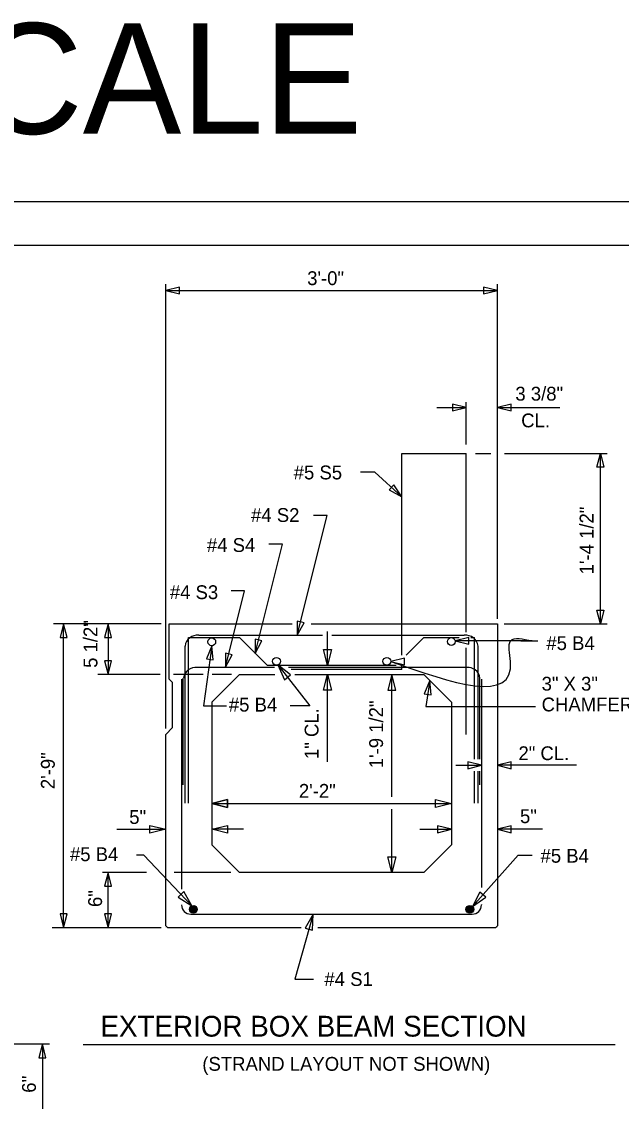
# Model space of a CAD drawing. Extents: x -38 to 94, y -165 to 80.
# Drawn here: x -18.57 to -13.15, y -151.14 to -141.37 of the extents above; entities that cross this region are included whole.
import ezdxf

# ---------------------------------------------------------------- set-up
doc = ezdxf.new("R2010")
doc.units = 0
for name, color, linetype in [('Arrowhead Terminators', 7, 'Continuous'), ('Arrowhead Terminators CELL', 7, 'Continuous'), ('Box Beam', 7, 'Continuous'), ('Dimension Lines', 7, 'Continuous'), ('Plan Sheet CELL', 7, 'Continuous'), ('Plot Shape CELL', 7, 'Continuous'), ('Rebar Lines', 7, 'Continuous'), ('Subtitle Text', 7, 'Continuous'), ('Text', 7, 'Continuous'), ('User Information Notes', 7, 'Continuous')]:
    doc.layers.add(name, color=color, linetype=linetype)

msp = doc.modelspace()

# ---------------------------------------------------------------- linework, layer by layer
at = {"layer": 'Arrowhead Terminators'}
for points in [[(-13.3685, -145.4052), (-13.3373, -145.2802), (-13.306, -145.4052)], [(-13.306, -146.6968), (-13.3373, -146.8218), (-13.3685, -146.6968)], [(-15.7707, -147.0532), (-15.8065, -147.1963), (-15.8423, -147.0532)], [(-15.2334, -147.1624), (-15.1084, -147.1936), (-15.1084, -147.1311)], [(-16.255, -147.194), (-16.1952, -147.3282), (-16.1391, -147.2843)], [(-15.8423, -147.4232), (-15.8065, -147.2802), (-15.7707, -147.4232)], [(-15.2232, -147.2802), (-15.2588, -147.4227), (-15.1875, -147.4227)], [(-16.7095, -148.4838), (-16.8525, -148.4481), (-16.7095, -148.4124)], [(-16.7095, -148.4124), (-16.8525, -148.4481), (-16.7095, -148.4838)], [(-14.8286, -148.4124), (-14.6856, -148.4481), (-14.8286, -148.4838)], [(-17.4122, -148.6452), (-17.2692, -148.681), (-17.4122, -148.7168)], [(-16.7095, -148.7168), (-16.8525, -148.681), (-16.7095, -148.6452)], [(-15.1874, -148.9288), (-15.2232, -149.0718), (-15.2589, -148.9288)], [(-17.0336, -149.3729), (-17.1058, -149.245), (-17.1575, -149.294)], [(-14.4956, -149.3786), (-14.374, -149.2962), (-14.4271, -149.2487)], [(-15.936, -149.4482), (-16.009, -149.5757), (-15.9404, -149.5951)], [(-18.3841, -150.6233), (-18.4153, -150.7483), (-18.3528, -150.7483)]]:
    msp.add_lwpolyline(points, close=True, dxfattribs=at)
at = {"layer": 'Arrowhead Terminators CELL'}
for points in [[(-17.2692, -143.8054), (-17.1442, -143.8367), (-17.1442, -143.7742)], [(-14.2689, -143.8054), (-14.3939, -143.7742), (-14.3939, -143.8367)], [(-14.5502, -144.8644), (-14.6752, -144.8331), (-14.6752, -144.8956)], [(-14.2689, -144.8644), (-14.1439, -144.8956), (-14.1439, -144.8331)], [(-15.1335, -145.6713), (-15.2052, -145.5642), (-15.2471, -145.6105)], [(-18.1922, -146.8218), (-18.2234, -146.9468), (-18.1609, -146.9468)], [(-17.7902, -146.8218), (-17.8214, -146.9468), (-17.7589, -146.9468)], [(-16.0786, -146.9258), (-16.0182, -146.812), (-16.0788, -146.797)], [(-14.651, -146.9753), (-14.526, -147.0066), (-14.526, -146.9441)], [(-16.8525, -147.02), (-16.9006, -147.1395), (-16.8387, -147.1481)], [(-16.4592, -147.0895), (-16.3988, -146.9757), (-16.4594, -146.9607)], [(-16.7275, -147.2151), (-16.6671, -147.1013), (-16.7277, -147.0863)], [(-17.7902, -147.2802), (-17.7589, -147.1552), (-17.8214, -147.1552)], [(-14.8808, -147.3351), (-14.9307, -147.4539), (-14.8689, -147.4634)], [(-14.4119, -148.1013), (-14.5369, -148.07), (-14.5369, -148.1325)], [(-14.2689, -148.1013), (-14.1439, -148.1325), (-14.1439, -148.07)], [(-14.6856, -148.681), (-14.8106, -148.6498), (-14.8106, -148.7123)], [(-14.2689, -148.681), (-14.1439, -148.7123), (-14.1439, -148.6498)], [(-17.7902, -149.0718), (-17.8214, -149.1968), (-17.7589, -149.1968)], [(-18.1922, -149.5718), (-18.1609, -149.4468), (-18.2234, -149.4468)], [(-17.7902, -149.5718), (-17.7589, -149.4468), (-17.8214, -149.4468)]]:
    msp.add_lwpolyline(points, close=True, dxfattribs=at)
at = {"layer": 'Box Beam'}
for p, q in [((-17.238, -147.3219), (-17.238, -146.8218)), ((-17.238, -146.8218), (-16.126, -146.8218)), ((-15.9532, -146.8218), (-14.2689, -146.8218)), ((-14.2689, -146.8218), (-14.2689, -149.554)), ((-17.2067, -147.3531), (-17.238, -147.3219)), ((-16.8525, -147.5303), (-16.6024, -147.2802)), ((-16.6024, -147.2802), (-16.2814, -147.2802)), ((-16.102, -147.2802), (-14.9356, -147.2802)), ((-14.9356, -147.2802), (-14.6856, -147.5303)), ((-17.2067, -147.7594), (-17.2067, -147.3531)), ((-16.8525, -147.5303), (-16.8525, -148.8218)), ((-14.6856, -147.5303), (-14.6856, -148.8218)), ((-17.2692, -147.8219), (-17.2067, -147.7594)), ((-17.2692, -149.554), (-17.2692, -147.8219)), ((-16.6024, -149.0718), (-16.8525, -148.8218)), ((-14.6856, -148.8218), (-14.9356, -149.0718)), ((-14.9356, -149.0718), (-16.6024, -149.0718)), ((-17.2692, -149.554), (-17.2513, -149.5718)), ((-16.0429, -149.5718), (-17.2513, -149.5718)), ((-14.2867, -149.5718), (-15.8938, -149.5718)), ((-14.2688, -149.554), (-14.2867, -149.5718))]:
    msp.add_line(p, q, dxfattribs=at)
at = {"layer": 'Dimension Lines'}
for p, q in [((-17.2692, -147.7691), (-17.2692, -143.7487)), ((-17.2692, -143.8054), (-14.2689, -143.8054)), ((-14.2689, -146.7758), (-14.2689, -143.7487)), ((-14.8155, -144.8644), (-14.5502, -144.8644)), ((-14.5502, -145.1981), (-14.5502, -144.8159)), ((-14.2689, -144.8644), (-13.7045, -144.8644)), ((-14.4681, -145.2802), (-14.3278, -145.2802)), ((-14.2051, -145.2802), (-13.2752, -145.2802)), ((-13.3373, -146.8218), (-13.3373, -145.2802)), ((-17.3095, -146.8218), (-18.2832, -146.8218)), ((-18.1922, -149.5718), (-18.1922, -146.8218)), ((-17.7902, -146.8218), (-17.7902, -147.2802)), ((-14.2064, -146.8218), (-13.2752, -146.8218)), ((-15.8065, -147.1963), (-15.8065, -146.8908)), ((-13.955, -146.9753), (-14.651, -146.9753)), ((-17.3186, -147.2802), (-17.8841, -147.2802)), ((-16.9303, -147.2802), (-17.1974, -147.2802)), ((-16.674, -147.2802), (-16.8504, -147.2802)), ((-15.8065, -148.0719), (-15.8065, -147.2802)), ((-15.2232, -148.3888), (-15.2232, -147.2802)), ((-14.644, -148.1013), (-14.4119, -148.1013)), ((-13.554, -148.1013), (-14.2689, -148.1013)), ((-16.8525, -148.4481), (-14.6856, -148.4481)), ((-15.2232, -149.0718), (-15.2232, -148.4985)), ((-17.7109, -148.681), (-17.2692, -148.681)), ((-16.5664, -148.681), (-16.8525, -148.681)), ((-14.9717, -148.681), (-14.6856, -148.681)), ((-13.8599, -148.681), (-14.2689, -148.681)), ((-14.0822, -148.9164), (-13.9553, -148.9164)), ((-17.4438, -149.0718), (-17.8398, -149.0718)), ((-17.7902, -149.5718), (-17.7902, -149.0718)), ((-16.6793, -149.0718), (-17.1938, -149.0718)), ((-15.936, -149.4482), (-16.1025, -150.0382)), ((-17.3095, -149.5718), (-18.2949, -149.5718)), ((-16.1025, -150.0382), (-15.9338, -150.0382)), ((-19.0939, -150.6233), (-18.3216, -150.6233)), ((-18.3841, -150.6233), (-18.3841, -151.3733))]:
    msp.add_line(p, q, dxfattribs=at)
for points in [[(-15.1335, -145.6713), (-15.3789, -145.4491), (-15.5063, -145.4491)], [(-16.0786, -146.9258), (-15.8097, -145.8428), (-15.9321, -145.8428)], [(-16.4592, -147.0895), (-16.214, -146.1018), (-16.3364, -146.1018)], [(-16.7275, -147.2151), (-16.5557, -146.5231), (-16.6781, -146.5231)], [(-16.8525, -147.02), (-16.9277, -147.564), (-16.7201, -147.564)], [(-14.0561, -146.9753), (-13.902, -146.9753)], [(-16.255, -147.194), (-15.9653, -147.564), (-16.1448, -147.564)], [(-14.8808, -147.3351), (-14.9169, -147.5696), (-13.9252, -147.5696)], [(-17.0336, -149.3729), (-17.4661, -148.9164), (-17.5348, -148.9164)], [(-14.4956, -149.3786), (-14.0822, -148.9164)]]:
    msp.add_lwpolyline(points, dxfattribs=at)
msp.add_spline([(-15.2334, -147.1624), (-14.1496, -147.1624), (-14.1496, -146.9753), (-13.955, -146.9753)], degree=3, dxfattribs=at)
at = {"layer": 'Plan Sheet CELL'}
msp.add_line((-32.4443, -143.3938), (-0.4439, -143.3938), dxfattribs=at)
at = {"layer": 'Plot Shape CELL'}
msp.add_lwpolyline([(-33.4983, -142.9999), (-0.4352, -142.9999), (-0.4352, -164.9999), (-33.4983, -164.9999)], close=True, dxfattribs=at)
at = {"layer": 'Rebar Lines'}
for p, q in [((-15.1335, -145.2802), (-14.5502, -145.2802)), ((-15.1335, -147.1064), (-15.1335, -145.2802)), ((-14.5502, -146.8982), (-14.5502, -145.2802)), ((-17.0628, -146.9463), (-16.6025, -146.9463)), ((-17.0628, -148.4443), (-17.0628, -146.9463)), ((-16.9698, -146.9258), (-15.85, -146.9258)), ((-16.6025, -146.9463), (-16.3524, -147.1963)), ((-15.7677, -146.9258), (-14.5691, -146.9258)), ((-14.9356, -146.9463), (-15.0948, -147.1054)), ((-14.9356, -146.9463), (-14.616, -146.9463)), ((-14.5104, -146.9463), (-14.4754, -146.9463)), ((-14.4754, -148.0472), (-14.4754, -146.9463)), ((-17.0941, -148.4443), (-17.0941, -147.0226)), ((-14.5502, -147.8218), (-14.5502, -147.0391)), ((-14.4441, -148.0472), (-14.4441, -147.0226)), ((-16.9821, -147.2151), (-16.2839, -147.2151)), ((-16.3524, -147.1963), (-15.1857, -147.1963)), ((-16.1599, -147.2151), (-14.5252, -147.2151)), ((-15.1335, -147.2346), (-16.1335, -147.2346)), ((-15.1335, -147.2346), (-15.1335, -147.2037)), ((-17.1254, -147.3219), (-17.1254, -149.2229)), ((-17.1106, -148.2802), (-17.1106, -147.3131)), ((-14.4279, -148.0472), (-14.4279, -147.3098)), ((-14.4128, -147.3219), (-14.4128, -149.2091)), ((-14.4754, -148.4443), (-14.4754, -148.1561)), ((-14.4441, -148.4443), (-14.4441, -148.1561)), ((-14.4279, -148.2802), (-14.4279, -148.1561)), ((-14.4128, -149.3604), (-14.4128, -149.3648)), ((-17.042, -149.4482), (-14.4962, -149.4482))]:
    msp.add_line(p, q, dxfattribs=at)
for points in [[(-17.0211, -149.3718), (-17.0084, -149.3743), (-16.9977, -149.3815), (-16.9906, -149.3922), (-16.988, -149.4049), (-16.9906, -149.4175), (-16.9977, -149.4282), (-17.0084, -149.4354), (-17.0211, -149.4379), (-17.0338, -149.4354), (-17.0446, -149.4282), (-17.0517, -149.4175), (-17.0542, -149.4049), (-17.0517, -149.3922), (-17.0446, -149.3815), (-17.0338, -149.3743), (-17.0211, -149.3718), (-17.0211, -149.4049), (-17.0211, -149.4379), (-17.0084, -149.4354), (-17.0211, -149.4049), (-16.9977, -149.4282), (-16.9906, -149.4175), (-17.0211, -149.4049), (-16.988, -149.4049), (-16.9906, -149.3922), (-17.0211, -149.4049), (-16.9977, -149.3815), (-17.0084, -149.3743), (-17.0211, -149.4049), (-17.0338, -149.3743), (-17.0446, -149.3815), (-17.0211, -149.4049), (-17.0517, -149.3922), (-17.0542, -149.4049), (-17.0211, -149.4049), (-17.0517, -149.4175), (-17.0446, -149.4282), (-17.0211, -149.4049), (-17.0338, -149.4354)], [(-14.517, -149.3718), (-14.5043, -149.3743), (-14.4936, -149.3815), (-14.4865, -149.3922), (-14.4839, -149.4049), (-14.4865, -149.4175), (-14.4936, -149.4282), (-14.5043, -149.4354), (-14.517, -149.4379), (-14.5297, -149.4354), (-14.5405, -149.4282), (-14.5475, -149.4175), (-14.5501, -149.4049), (-14.5475, -149.3922), (-14.5405, -149.3815), (-14.5297, -149.3743), (-14.517, -149.3718), (-14.517, -149.4049), (-14.517, -149.4379), (-14.5043, -149.4354), (-14.517, -149.4049), (-14.4936, -149.4282), (-14.4865, -149.4175), (-14.517, -149.4049), (-14.4839, -149.4049), (-14.4865, -149.3922), (-14.517, -149.4049), (-14.4936, -149.3815), (-14.5043, -149.3743), (-14.517, -149.4049), (-14.5297, -149.3743), (-14.5405, -149.3815), (-14.517, -149.4049), (-14.5475, -149.3922), (-14.5501, -149.4049), (-14.517, -149.4049), (-14.5475, -149.4175), (-14.5405, -149.4282), (-14.517, -149.4049), (-14.5297, -149.4354)]]:
    msp.add_lwpolyline(points, dxfattribs=at)
for centre in [(-16.8525, -146.9847), (-14.6856, -146.9821), (-16.2674, -147.1611), (-15.2686, -147.1611), (-17.0194, -149.4052), (-14.5187, -149.4052)]:
    msp.add_circle(centre, 0.0352, dxfattribs=at)
for centre, radius, start, end in [((-16.9835, -147.0363), 0.1114, 82.91815, 172.91815), ((-14.5549, -147.0367), 0.1118, 7.25072, 97.25072), ((-16.9968, -147.3272), 0.1114, 82.91815, 172.91815), ((-14.5373, -147.3275), 0.1118, 7.25072, 97.25072), ((-17.042, -149.3648), 0.0834, 180, 270), ((-14.4962, -149.3648), 0.0834, 270, 360)]:
    msp.add_arc(centre, radius, start, end, dxfattribs=at)
at = {"layer": 'Subtitle Text'}
msp.add_line((-18.015, -150.6289), (-13.2046, -150.6289), dxfattribs=at)
at = {"layer": 'User Information Notes'}
for p, q in [((-17.2692, -149.5718), (-17.2692, -149.5718)), ((-14.2689, -149.5718), (-14.2689, -149.5718))]:
    msp.add_line(p, q, dxfattribs=at)
for centre in [(-17.0194, -149.4052), (-14.5186, -149.4052), (-14.5187, -149.4052)]:
    msp.add_circle(centre, 0.0352, dxfattribs=at)

# ---------------------------------------------------------------- texts
at = {"layer": 'Subtitle Text'}
msp.add_text('EXTERIOR BOX BEAM SECTION', height=0.188, dxfattribs=at).set_placement((-17.8595, -150.557))
at = {"layer": 'Text'}
for s, height, p in [('3\'-0"', 0.12521, (-15.9895, -143.7567)), ('3 3/8"', 0.12521, (-14.1064, -144.802)), ('CL.', 0.12521, (-14.0538, -145.0437)), ('#5 S5', 0.12521, (-16.1114, -145.5148)), ('#4 S2', 0.12521, (-16.4971, -145.9)), ('#4 S4', 0.12521, (-16.8963, -146.1714)), ('#4 S3', 0.125, (-17.2316, -146.5981)), ('#5 B4', 0.12521, (-13.8261, -147.0589)), ('3" X 3"', 0.125, (-13.8688, -147.4261)), ('#5 B4', 0.12521, (-16.6979, -147.6157)), ('CHAMFER (TYP.)', 0.125, (-13.8688, -147.6141)), ('2" CL.', 0.125, (-14.0784, -148.0554)), ('2\'-2"', 0.12521, (-16.0646, -148.3961)), ('5"', 0.12521, (-17.5988, -148.6326)), ('5"', 0.125, (-14.0646, -148.6251)), ('#5 B4', 0.12521, (-18.1351, -148.9693)), ('#5 B4', 0.12521, (-13.8787, -148.9833)), ('#4 S1', 0.12521, (-15.8337, -150.0988)), ('(STRAND LAYOUT NOT SHOWN)', 0.125206, (-16.9379, -150.8663))]:
    msp.add_text(s, height=height, dxfattribs=at).set_placement(p)
for s, height, p in [('1\'-4 1/2"', 0.12521, (-13.3997, -146.3739)), ('5 1/2"', 0.12521, (-17.887, -147.2204)), ('1\'-9 1/2"', 0.12521, (-15.3035, -148.1284)), ('1" CL.', 0.12521, (-15.8869, -148.0453)), ('2\'-9"', 0.12521, (-18.2726, -148.3176)), ('6"', 0.12521, (-17.845, -149.3845)), ("6''", 0.125, (-18.4433, -151.0655))]:
    msp.add_text(s, height=height, rotation=90, dxfattribs=at).set_placement(p)
at = {"layer": 'User Information Notes'}
msp.add_text('1" SCALE', height=1, dxfattribs=at).set_placement((-21.467, -142.3871))

doc.saveas('drawing.dxf')
